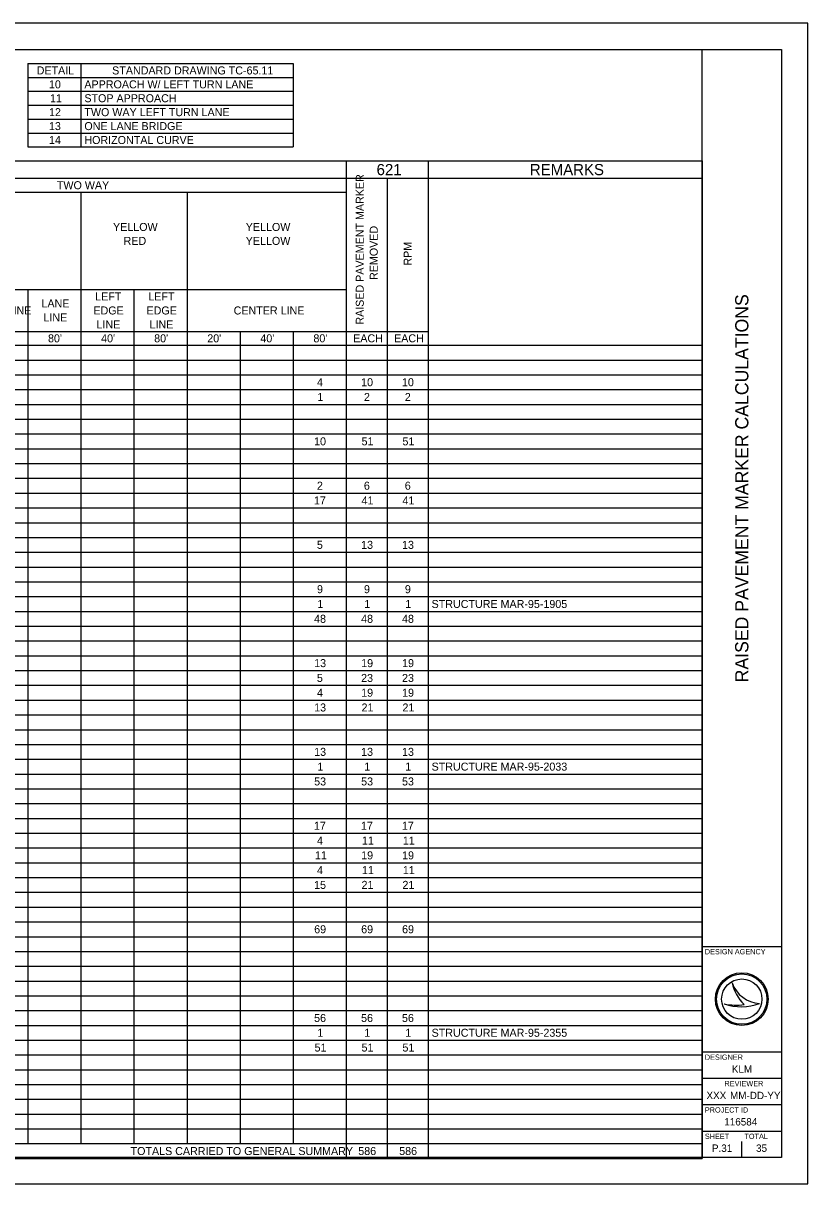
# Model space of a CAD drawing. Extents: x 0 to 34, y 0 to 22.
# Drawn here: x 19.14 to 34, y 0 to 22 of the extents above; entities that cross this region are included whole.
import ezdxf

# ---------------------------------------------------------------- set-up
doc = ezdxf.new("R2010")
doc.units = 0
for name, color, linetype in [('SH_Border', 7, 'Continuous'), ('SH_Cut_Line', 7, 'Continuous'), ('SH_Data', 7, 'Continuous'), ('SH_Text', 7, 'Continuous')]:
    doc.layers.add(name, color=color, linetype=linetype)

msp = doc.modelspace()

# ---------------------------------------------------------------- linework, layer by layer
at = {"layer": 'SH_Border'}
for p, q in [((32, 0.5), (32, 21.5)), ((32, 4.5), (33.5, 4.5)), ((32, 2.5), (33.5, 2.5)), ((32, 2), (33.5, 2)), ((32, 1.5), (33.5, 1.5)), ((32, 1), (33.5, 1))]:
    msp.add_line(p, q, dxfattribs=at)
msp.add_lwpolyline([(1.5, 21.5), (33.5, 21.5), (33.5, 0.5), (1.5, 0.5)], close=True, dxfattribs=at)
at = {"layer": 'SH_Cut_Line'}
msp.add_lwpolyline([(0, 0), (34, 0), (34, 22), (0, 22)], close=True, dxfattribs=at)
at = {"layer": 'SH_Data'}
for p, q in [((32.567, 3.81), (32.567, 3.81)), ((32.417, 3.41), (32.417, 3.41)), ((32.75, 3.5), (32.75, 3.5)), ((33.087, 3.419), (33.087, 3.419)), ((32.375, 0.675), (32.375, 0.675)), ((32.75, 0.5), (32.75, 0.8))]:
    msp.add_line(p, q, dxfattribs=at)
for radius in [0.5, 0.477, 0.477, 0.382]:
    msp.add_circle((32.75, 3.5), radius, dxfattribs=at)
for centre, radius, start, end in [((33.116, 3.998), 0.58, 198.9257, 198.9319), ((33.347, 3.97), 0.796, 191.6379, 191.6421), ((33.116, 3.998), 0.58, 198.9319, 267.1657), ((33.347, 3.97), 0.796, 191.6421, 226.0947), ((32.739, 4.37), 1.013, 251.4576, 290.0832), ((32.648, 4.654), 1.266, 259.4964, 259.4995), ((32.739, 4.37), 1.013, 251.4527, 251.4576), ((32.648, 4.654), 1.266, 259.4995, 276.6672)]:
    msp.add_arc(centre, radius, start, end, dxfattribs=at)
at = {"layer": 'SH_Text'}
for p, q in [((19.223, 21.237), (24.251, 21.237)), ((19.223, 21.237), (19.223, 19.654)), ((20.229, 21.237), (20.229, 19.654)), ((24.251, 21.237), (24.251, 19.654)), ((19.223, 20.973), (24.251, 20.973)), ((19.223, 20.709), (24.251, 20.709)), ((19.223, 20.446), (24.251, 20.446)), ((19.223, 20.182), (24.251, 20.182)), ((19.223, 19.918), (24.251, 19.918)), ((19.223, 19.654), (24.251, 19.654)), ((1.5, 19.39), (32, 19.39)), ((25.257, 19.39), (25.257, 0.48)), ((26.807, 19.39), (26.807, 0.48)), ((32, 19.39), (32, 0.48)), ((1.5, 19.061), (32, 19.061)), ((26.032, 19.061), (26.032, 0.761)), ((10.172, 18.797), (25.257, 18.797)), ((20.229, 18.797), (20.229, 0.761)), ((22.24, 18.797), (22.24, 0.761)), ((10.172, 16.95), (25.257, 16.95)), ((19.223, 16.95), (19.223, 0.761)), ((21.234, 16.95), (21.234, 0.761)), ((10.172, 16.159), (26.807, 16.159)), ((23.246, 16.159), (23.246, 0.761)), ((24.251, 16.159), (24.251, 0.761)), ((1.5, 15.895), (32, 15.895)), ((1.5, 15.615), (32, 15.615)), ((1.5, 15.335), (32, 15.335)), ((1.5, 15.054), (32, 15.054)), ((1.5, 14.774), (32, 14.774)), ((1.5, 14.494), (32, 14.494)), ((1.5, 14.214), (32, 14.214)), ((1.5, 13.933), (32, 13.933)), ((1.5, 13.653), (32, 13.653)), ((1.5, 13.373), (32, 13.373)), ((1.5, 13.093), (32, 13.093)), ((1.5, 12.812), (32, 12.812)), ((1.5, 12.532), (32, 12.532)), ((1.5, 12.252), (32, 12.252)), ((1.5, 11.972), (32, 11.972)), ((1.5, 11.691), (32, 11.691)), ((1.5, 11.411), (32, 11.411)), ((1.5, 11.131), (32, 11.131)), ((1.5, 10.85), (32, 10.85)), ((1.5, 10.57), (32, 10.57)), ((1.5, 10.29), (32, 10.29)), ((1.5, 10.01), (32, 10.01)), ((1.5, 9.729), (32, 9.729)), ((1.5, 9.449), (32, 9.449)), ((1.5, 9.169), (32, 9.169)), ((1.5, 8.889), (32, 8.889)), ((1.5, 8.608), (32, 8.608)), ((1.5, 8.328), (32, 8.328)), ((1.5, 8.048), (32, 8.048)), ((1.5, 7.767), (32, 7.767)), ((1.5, 7.487), (32, 7.487)), ((1.5, 7.207), (32, 7.207)), ((1.5, 6.927), (32, 6.927)), ((1.5, 6.646), (32, 6.646)), ((1.5, 6.366), (32, 6.366)), ((1.5, 6.086), (32, 6.086)), ((1.5, 5.806), (32, 5.806)), ((1.5, 5.525), (32, 5.525)), ((1.5, 5.245), (32, 5.245)), ((1.5, 4.965), (32, 4.965)), ((1.5, 4.684), (32, 4.684)), ((1.5, 4.404), (32, 4.404)), ((1.5, 4.124), (32, 4.124)), ((1.5, 3.844), (32, 3.844)), ((1.5, 3.563), (32, 3.563)), ((1.5, 3.283), (32, 3.283)), ((1.5, 3.003), (32, 3.003)), ((1.5, 2.723), (32, 2.723)), ((1.5, 2.442), (32, 2.442)), ((1.5, 2.162), (32, 2.162)), ((1.5, 1.882), (32, 1.882)), ((1.5, 1.602), (32, 1.602)), ((1.5, 1.321), (32, 1.321)), ((1.5, 1.041), (32, 1.041)), ((1.5, 0.761), (32, 0.761)), ((26.032, 0.761), (26.032, 0.48)), ((1.5, 0.48), (32, 0.48))]:
    msp.add_line(p, q, dxfattribs=at)

# ---------------------------------------------------------------- texts
at = {"layer": 'SH_Data'}
msp.add_text('RAISED PAVEMENT MARKER CALCULATIONS', height=0.25, rotation=90, dxfattribs=at).set_placement((32.875, 9.506))
for s, height, p in [('DESIGN AGENCY', 0.1, (32.05, 4.35)), ('DESIGNER', 0.1, (32.05, 2.35)), ('KLM', 0.14, (32.561, 2.105)), ('REVIEWER', 0.1, (32.422, 1.85)), ('XXX', 0.14, (32.081, 1.605)), ('MM-DD-YY', 0.14, (32.527, 1.605)), ('PROJECT ID', 0.1, (32.05, 1.35)), ('116584', 0.14, (32.418, 1.105)), ('SHEET', 0.1, (32.05, 0.85)), ('TOTAL', 0.1, (32.8, 0.85)), ('P.31', 0.14, (32.184, 0.605)), ('35', 0.14, (33.02, 0.605))]:
    msp.add_text(s, height=height, dxfattribs=at).set_placement(p)
at = {"layer": 'SH_Text'}
for s, height, p in [('DETAIL', 0.1517, (19.391, 21.029)), ('STANDARD DRAWING TC-65.11', 0.15168, (20.821, 21.029)), ('10', 0.1517, (19.624, 20.765)), ('APPROACH W/ LEFT TURN LANE', 0.15168, (20.295, 20.765)), ('11', 0.1517, (19.644, 20.502)), ('STOP APPROACH', 0.15168, (20.295, 20.502)), ('12', 0.1517, (19.625, 20.238)), ('TWO WAY LEFT TURN LANE', 0.15168, (20.295, 20.238)), ('13', 0.1517, (19.624, 19.974)), ('ONE LANE BRIDGE', 0.15168, (20.295, 19.974)), ('14', 0.1517, (19.624, 19.71)), ('HORIZONTAL CURVE', 0.15168, (20.295, 19.71)), ('621', 0.2123, (25.831, 19.119)), ('REMARKS', 0.2123, (28.735, 19.119)), ('TWO WAY', 0.1517, (19.774, 18.853)), ('YELLOW', 0.1517, (20.838, 18.062)), ('YELLOW', 0.1517, (23.352, 18.062)), ('RED', 0.1517, (21.038, 17.798)), ('YELLOW', 0.1517, (23.352, 17.798)), ('LANE  ', 0.1517, (19.482, 16.612)), ('LEFT ', 0.1517, (20.5, 16.744)), ('LEFT ', 0.1517, (21.506, 16.744)), ('CHANNELIZING LINE', 0.15168, (17.274, 16.479)), ('EDGE  ', 0.1517, (20.466, 16.479)), ('EDGE  ', 0.1517, (21.472, 16.479)), ('CENTER LINE', 0.15168, (23.123, 16.479)), ('LINE', 0.1517, (19.519, 16.346)), ('LINE', 0.1517, (20.525, 16.213)), ('LINE', 0.1517, (21.53, 16.213)), ("80'", 0.1517, (19.606, 15.951)), ("40'", 0.1517, (20.612, 15.951)), ("80'", 0.1517, (21.617, 15.951)), ("20'", 0.1517, (22.623, 15.951)), ("40'", 0.1517, (23.629, 15.951)), ("80'", 0.1517, (24.634, 15.951)), ('EACH', 0.1517, (25.387, 15.951)), ('EACH', 0.1517, (26.162, 15.951)), ('4', 0.152, (24.702, 15.119)), ('10', 0.1517, (25.538, 15.119)), ('10', 0.1517, (26.312, 15.119)), ('1', 0.152, (24.709, 14.839)), ('2', 0.152, (25.591, 14.839)), ('2', 0.152, (26.366, 14.839)), ('10', 0.1517, (24.647, 13.998)), ('51', 0.1517, (25.546, 13.998)), ('51', 0.1517, (26.321, 13.998)), ('2', 0.152, (24.701, 13.157)), ('6', 0.152, (25.59, 13.157)), ('6', 0.152, (26.365, 13.157)), ('17', 0.1517, (24.644, 12.877)), ('41', 0.1517, (25.546, 12.877)), ('41', 0.1517, (26.321, 12.877)), ('5', 0.152, (24.7, 12.036)), ('13', 0.1517, (25.538, 12.036)), ('13', 0.1517, (26.313, 12.036)), ('9', 0.152, (24.702, 11.195)), ('9', 0.152, (25.592, 11.195)), ('9', 0.152, (26.367, 11.195)), ('1', 0.152, (24.709, 10.915)), ('1', 0.152, (25.599, 10.915)), ('1', 0.152, (26.374, 10.915)), ('STRUCTURE MAR-95-1905', 0.15168, (26.873, 10.915)), ('48', 0.1517, (24.647, 10.634)), ('48', 0.1517, (25.538, 10.634)), ('48', 0.1517, (26.313, 10.634)), ('13', 0.1517, (24.648, 9.794)), ('19', 0.1517, (25.539, 9.794)), ('19', 0.1517, (26.314, 9.794)), ('5', 0.152, (24.7, 9.513)), ('23', 0.1517, (25.538, 9.513)), ('23', 0.1517, (26.313, 9.513)), ('4', 0.152, (24.702, 9.233)), ('19', 0.1517, (25.539, 9.233)), ('19', 0.1517, (26.314, 9.233)), ('13', 0.1517, (24.648, 8.953)), ('21', 0.1517, (25.546, 8.953)), ('21', 0.1517, (26.321, 8.953)), ('13', 0.1517, (24.648, 8.112)), ('13', 0.1517, (25.538, 8.112)), ('13', 0.1517, (26.313, 8.112)), ('1', 0.152, (24.709, 7.832)), ('1', 0.152, (25.599, 7.832)), ('1', 0.152, (26.374, 7.832)), ('STRUCTURE MAR-95-2033', 0.15168, (26.873, 7.832)), ('53', 0.1517, (24.648, 7.551)), ('53', 0.1517, (25.538, 7.551)), ('53', 0.1517, (26.313, 7.551)), ('17', 0.1517, (24.644, 6.711)), ('17', 0.1517, (25.535, 6.711)), ('17', 0.1517, (26.31, 6.711)), ('4', 0.152, (24.702, 6.43)), ('11', 0.1517, (25.553, 6.43)), ('11', 0.1517, (26.328, 6.43)), ('11', 0.1517, (24.663, 6.15)), ('19', 0.1517, (25.539, 6.15)), ('19', 0.1517, (26.314, 6.15)), ('4', 0.152, (24.702, 5.87)), ('11', 0.1517, (25.553, 5.87)), ('11', 0.1517, (26.328, 5.87)), ('15', 0.1517, (24.647, 5.59)), ('21', 0.1517, (25.546, 5.59)), ('21', 0.1517, (26.321, 5.59)), ('69', 0.1517, (24.649, 4.749)), ('69', 0.1517, (25.539, 4.749)), ('69', 0.1517, (26.314, 4.749)), ('56', 0.1517, (24.647, 3.067)), ('56', 0.1517, (25.537, 3.067)), ('56', 0.1517, (26.312, 3.067)), ('1', 0.152, (24.709, 2.787)), ('1', 0.152, (25.599, 2.787)), ('1', 0.152, (26.374, 2.787)), ('STRUCTURE MAR-95-2355', 0.15168, (26.873, 2.787)), ('51', 0.1517, (24.656, 2.507)), ('51', 0.1517, (25.546, 2.507)), ('51', 0.1517, (26.321, 2.507)), ('TOTALS CARRIED TO GENERAL SUMMARY', 0.15168, (21.17, 0.545)), ('586', 0.1517, (25.484, 0.545)), ('586', 0.1517, (26.259, 0.545))]:
    msp.add_text(s, height=height, dxfattribs=at).set_placement(p)
for s, height, p in [('RAISED PAVEMENT MARKER ', 0.15168, (25.588, 16.286)), ('REMOVED', 0.1517, (25.853, 17.133)), ('RPM', 0.1517, (26.495, 17.405))]:
    msp.add_text(s, height=height, rotation=90, dxfattribs=at).set_placement(p)

doc.saveas('drawing.dxf')
